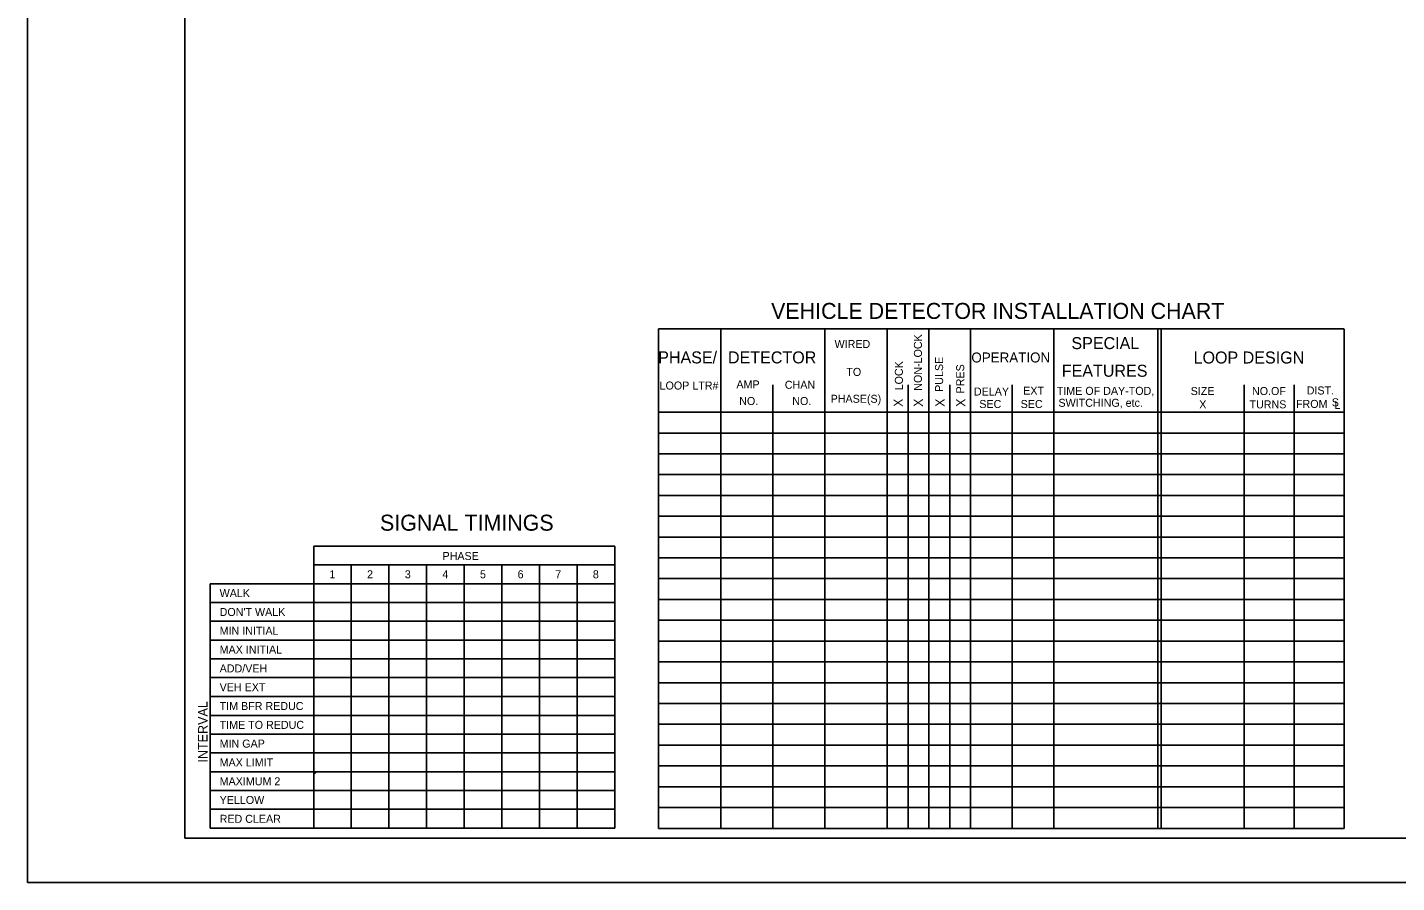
# Model space of a CAD drawing. Extents: x 0 to 3.01, y -0.05 to 1.83.
# Drawn here: x 0 to 1.467, y 0 to 0.917 of the extents above; entities that cross this region are included whole.
import ezdxf

# ---------------------------------------------------------------- set-up
doc = ezdxf.new("R2010")
doc.units = 0
for name, color, linetype in [('RD_SHT_IplotShp', 7, 'Continuous'), ('TR_TS_Border', 7, 'Continuous'), ('TR_TS_Loop Detector Chart', 7, 'Continuous'), ('TR_TS_Phase1', 7, 'Continuous'), ('TR_TS_Phase2', 7, 'Continuous'), ('TR_TS_Phase3', 7, 'Continuous'), ('TR_TS_Phase4', 7, 'Continuous'), ('TR_TS_Phase5', 7, 'Continuous'), ('TR_TS_Phase6', 7, 'Continuous'), ('TR_TS_Phase7', 7, 'Continuous'), ('TR_TS_Phase8', 7, 'Continuous')]:
    doc.layers.add(name, color=color, linetype=linetype)

msp = doc.modelspace()

# ---------------------------------------------------------------- linework, layer by layer
at = {"layer": 'RD_SHT_IplotShp'}
msp.add_lwpolyline([(0, 0), (3, 0), (3, 1.8333), (0, 1.8333)], close=True, dxfattribs=at)
at = {"layer": 'TR_TS_Border'}
for p, q in [((0, 0), (0, 1.8333)), ((0.1686, 1.7754), (0.1686, 0.0475)), ((0.3068, 0.3607), (0.6293, 0.3607)), ((0.3068, 0.3607), (0.3068, 0.3204)), ((0.6293, 0.3607), (0.6293, 0.0585)), ((0.3068, 0.3406), (0.6293, 0.3406)), ((0.3471, 0.3406), (0.3471, 0.0585)), ((0.3874, 0.3406), (0.3874, 0.0585)), ((0.4278, 0.3406), (0.4278, 0.0585)), ((0.4681, 0.3406), (0.4681, 0.0585)), ((0.5083, 0.3406), (0.5083, 0.0585)), ((0.5486, 0.3406), (0.5486, 0.0585)), ((0.589, 0.3406), (0.589, 0.0585)), ((0.1959, 0.3204), (0.1959, 0.0585)), ((0.1959, 0.3204), (0.3068, 0.3204)), ((0.3068, 0.3204), (0.3068, 0.1189)), ((0.3068, 0.3204), (0.6293, 0.3204)), ((0.1959, 0.3003), (0.6293, 0.3003)), ((0.1959, 0.2801), (0.6293, 0.2801)), ((0.1959, 0.26), (0.6293, 0.26)), ((0.1959, 0.2398), (0.6293, 0.2398)), ((0.1959, 0.2197), (0.6293, 0.2197)), ((0.1959, 0.1995), (0.6293, 0.1995)), ((0.1959, 0.1793), (0.6293, 0.1793)), ((0.1959, 0.1592), (0.6293, 0.1592)), ((0.1959, 0.139), (0.6293, 0.139)), ((0.1959, 0.1189), (0.3068, 0.1189)), ((0.3068, 0.0585), (0.3068, 0.1189)), ((0.3068, 0.1189), (0.6293, 0.1189)), ((0.3068, 0.116), (0.3099, 0.1189)), ((0.1959, 0.0987), (0.6293, 0.0987)), ((0.1959, 0.0786), (0.6293, 0.0786)), ((0.1686, 0.0475), (2.9623, 0.0475)), ((0.1959, 0.0585), (0.6293, 0.0585)), ((0.0238, 0), (3, 0))]:
    msp.add_line(p, q, dxfattribs=at)
at = {"layer": 'TR_TS_Loop Detector Chart'}
for p, q in [((0.6761, 0.5934), (1.4109, 0.5934)), ((0.6761, 0.0581), (0.6761, 0.5934)), ((0.743, 0.0581), (0.743, 0.5934)), ((0.8545, 0.0581), (0.8545, 0.5934)), ((0.9214, 0.0581), (0.9214, 0.5935)), ((0.966, 0.0581), (0.966, 0.5932)), ((1.0106, 0.0581), (1.0106, 0.5934)), ((1.0998, 0.0581), (1.0998, 0.5932)), ((1.2113, 0.0581), (1.2113, 0.5932)), ((1.2147, 0.0581), (1.2147, 0.5931)), ((1.4109, 0.5932), (1.4109, 0.0581)), ((0.7988, 0.0581), (0.7988, 0.5336)), ((0.9437, 0.0581), (0.9437, 0.5334)), ((0.9883, 0.0581), (0.9883, 0.5334)), ((1.0552, 0.0581), (1.0552, 0.5334)), ((1.3039, 0.0581), (1.3039, 0.5334)), ((1.3574, 0.0581), (1.3574, 0.5334)), ((0.6761, 0.5042), (1.4109, 0.5042)), ((0.6761, 0.4819), (1.4109, 0.4819)), ((0.6761, 0.4596), (1.4109, 0.4596)), ((0.6761, 0.4373), (1.4109, 0.4373)), ((0.6761, 0.415), (1.4109, 0.415)), ((0.6761, 0.3927), (1.4109, 0.3927)), ((0.6761, 0.3704), (1.4109, 0.3704)), ((0.6761, 0.3481), (1.4109, 0.3481)), ((0.6761, 0.3258), (1.4109, 0.3258)), ((0.6761, 0.3035), (1.4109, 0.3035)), ((0.6761, 0.2812), (1.4109, 0.2812)), ((0.6761, 0.2589), (1.4109, 0.2589)), ((0.6761, 0.2366), (1.4109, 0.2366)), ((0.6761, 0.2143), (1.4109, 0.2143)), ((0.6761, 0.192), (1.4109, 0.192)), ((0.6761, 0.1697), (1.4109, 0.1697)), ((0.6761, 0.1473), (1.4109, 0.1473)), ((0.6761, 0.125), (1.4109, 0.125)), ((0.6761, 0.1027), (1.4109, 0.1027)), ((0.6761, 0.0804), (1.4109, 0.0804)), ((0.6761, 0.0581), (1.4109, 0.0581))]:
    msp.add_line(p, q, dxfattribs=at)

# ---------------------------------------------------------------- texts
at = {"layer": 'TR_TS_Border'}
for s, height, p in [('SIGNAL TIMINGS', 0.017156, (0.3778, 0.3772)), ('MAX INITIAL', 0.008578, (0.206, 0.2455))]:
    msp.add_text(s, height=height, dxfattribs=at).set_placement(p)
for s, height, rotation, p in [('PHASE', 0.00858, 360, (0.4448, 0.3458)), ('WALK', 0.00858, 360, (0.206, 0.306)), ("DON'T WALK", 0.00858, 360, (0.206, 0.2858)), ('MIN INITIAL', 0.008578, 360, (0.206, 0.2656)), ('ADD/VEH', 0.00858, 360, (0.206, 0.2253)), ('VEH EXT', 0.00858, 360, (0.206, 0.2052)), ('INTERVAL', 0.01008, 90, (0.193, 0.1286)), ('TIM BFR REDUC', 0.008578, 360, (0.206, 0.185)), ('TIME TO REDUC', 0.008578, 360, (0.206, 0.1648)), ('MIN GAP', 0.00858, 360, (0.206, 0.1447)), ('MAX LIMIT', 0.00858, 360, (0.206, 0.1245)), ('MAXIMUM 2', 0.00858, 360, (0.206, 0.1043)), ('YELLOW', 0.00858, 360, (0.206, 0.0843)), ('RED CLEAR', 0.00858, 360, (0.206, 0.0641))]:
    msp.add_text(s, height=height, rotation=rotation, dxfattribs=at).set_placement(p)
at = {"layer": 'TR_TS_Loop Detector Chart'}
for s, height, p in [('VEHICLE DETECTOR INSTALLATION CHART', 0.017156, (0.7969, 0.6042)), ('WIRED', 0.00858, (0.8649, 0.573)), ('SPECIAL', 0.01287, (1.1187, 0.5718)), ('PHASE/', 0.01287, (0.6759, 0.5565)), ('DETECTOR', 0.01287, (0.7507, 0.5565)), ('OPERATION', 0.01072, (1.0115, 0.5575)), ('LOOP DESIGN', 0.012867, (1.2496, 0.5564)), ('TO', 0.00858, (0.8775, 0.5431)), ('FEATURES', 0.01287, (1.1084, 0.5422)), ('LOOP LTR#', 0.00858, (0.6774, 0.5285)), ('AMP', 0.00858, (0.7597, 0.5297)), ('CHAN', 0.00858, (0.8116, 0.5293)), ('DELAY', 0.00858, (1.0142, 0.5221)), ('EXT', 0.00858, (1.067, 0.523)), ('TIME OF DAY-TOD,', 0.008578, (1.103, 0.5228)), ('SIZE', 0.00858, (1.2465, 0.5226)), ('NO.OF', 0.00858, (1.3122, 0.5226)), ('DIST.', 0.00858, (1.3708, 0.5232)), ('NO.', 0.00858, (0.7627, 0.5119)), ('NO.', 0.00858, (0.8196, 0.5119)), ('PHASE(S)', 0.00858, (0.8607, 0.5143)), ('SEC', 0.00858, (1.02, 0.5087)), ('SEC', 0.00858, (1.0643, 0.5087)), ('SWITCHING, etc.', 0.008578, (1.1048, 0.51)), ('   X   ', 0.00858, (1.2461, 0.5083)), ('TURNS', 0.00858, (1.3095, 0.5083)), ('FROM', 0.00858, (1.3593, 0.5088)), ('S', 0.00858, (1.3977, 0.5105)), ('L', 0.00858, (1.4004, 0.5077))]:
    msp.add_text(s, height=height, dxfattribs=at).set_placement(p)
for s, height, p in [('NON-LOCK', 0.00858, (0.9585, 0.5272)), ('LOCK', 0.00858, (0.9381, 0.5276)), (' PULSE', 0.00858, (0.9812, 0.5228)), ('PRES', 0.00858, (1.0038, 0.5243)), ('X', 0.00972, (0.9379, 0.51)), ('X', 0.00981, (0.9595, 0.51)), ('X', 0.00981, (0.9828, 0.51)), ('X', 0.00981, (1.005, 0.51))]:
    msp.add_text(s, height=height, rotation=90, dxfattribs=at).set_placement(p)
at = {"layer": 'TR_TS_Phase1'}
msp.add_text('1', height=0.00858, rotation=360, dxfattribs=at).set_placement((0.3236, 0.3262))
at = {"layer": 'TR_TS_Phase2'}
msp.add_text('2', height=0.00858, rotation=360, dxfattribs=at).set_placement((0.364, 0.3262))
at = {"layer": 'TR_TS_Phase3'}
msp.add_text('3', height=0.00858, rotation=360, dxfattribs=at).set_placement((0.4044, 0.3262))
at = {"layer": 'TR_TS_Phase4'}
msp.add_text('4', height=0.00858, rotation=360, dxfattribs=at).set_placement((0.4446, 0.3262))
at = {"layer": 'TR_TS_Phase5'}
msp.add_text('5', height=0.00858, rotation=360, dxfattribs=at).set_placement((0.485, 0.3262))
at = {"layer": 'TR_TS_Phase6'}
msp.add_text('6', height=0.00858, rotation=360, dxfattribs=at).set_placement((0.5253, 0.3262))
at = {"layer": 'TR_TS_Phase7'}
msp.add_text('7', height=0.00858, rotation=360, dxfattribs=at).set_placement((0.5656, 0.3262))
at = {"layer": 'TR_TS_Phase8'}
msp.add_text('8', height=0.00858, rotation=360, dxfattribs=at).set_placement((0.6059, 0.3262))

doc.saveas('drawing.dxf')
